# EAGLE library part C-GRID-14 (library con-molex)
CONNECTOR wire to board 2.54 mm (0.100") pitch header
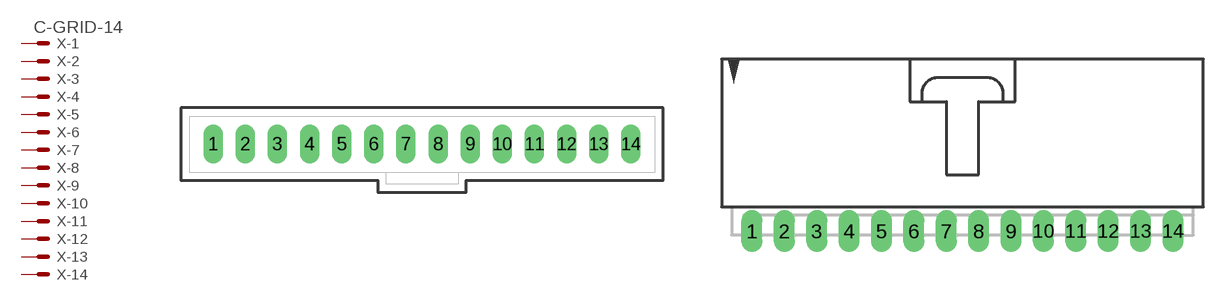
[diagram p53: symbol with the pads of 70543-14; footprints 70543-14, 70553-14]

Designator prefix X; gates -1=MV -2=M -3=M -4=M -5=M -6=M -7=M -8=M -9=M -10=M -11=M -12=M -13=M -14=M

## C-GRID-14-70543 (OC_FARNELL: unknown; OC_NEWARK: unknown)  [70543-14]
1  -1:S  pas
2  -2:S  pas
3  -3:S  pas
4  -4:S  pas
5  -5:S  pas
6  -6:S  pas
7  -7:S  pas
8  -8:S  pas
9  -9:S  pas
10  -10:S  pas
11  -11:S  pas
12  -12:S  pas
13  -13:S  pas
14  -14:S  pas

## C-GRID-14-70553 (OC_FARNELL: unknown; OC_NEWARK: unknown)  [70553-14]
Pads as for 70543-14

## C-GRID-14-74099 (OC_FARNELL: unknown; OC_NEWARK: unknown)  [74099-14]
Pads as for 70543-14

## C-GRID-14-15-91 (OC_FARNELL: unknown; OC_NEWARK: unknown)  [15-91-14]
Pads as for 70543-14

## Footprint 70543-14 (pad centres in mm)
C-Grid SL Connector vertical, 14 pin
drill 1.016 long: 1 -16.51,0; 2 -13.97,0; 3 -11.43,0; 4 -8.89,0; 5 -6.35,0; 6 -3.81,0; 7 -1.27,0; 8 1.27,0; 9 3.81,0; 10 6.35,0; 11 8.89,0; 12 11.43,0; 13 13.97,0; 14 16.51,0

## Footprint 70553-14 (pad centres in mm)
C-Grid SL Connector right angle, 14 pin
drill 1.092 long: 1 -16.51,-7.62; 2 -13.97,-7.62; 3 -11.43,-7.62; 4 -8.89,-7.62; 5 -6.35,-7.62; 6 -3.81,-7.62; 7 -1.27,-7.62; 8 1.27,-7.62; 9 3.81,-7.62; 10 6.35,-7.62; 11 8.89,-7.62; 12 11.43,-7.62; 13 13.97,-7.62; 14 16.51,-7.62

## Footprint 74099-14 (pad centres in mm)
C-Grid SL Connector vertical SMD, 14 pin
smd 1.27 x 3.175: 1 -16.51,-2.223; 2 -13.97,2.223; 3 -11.43,-2.223; 4 -8.89,2.223; 5 -6.35,-2.223; 6 -3.81,2.223; 7 -1.27,-2.223; 8 1.27,2.223; 9 3.81,-2.223; 10 6.35,2.223; 11 8.89,-2.223; 12 11.43,2.223; 13 13.97,-2.223; 14 16.51,2.223

## Footprint 15-91-14 (pad centres in mm)
C-Grid SL Connector right angle SMD, 14 pin
smd 1.651 x 5.334: 1 -16.51,-10.795; 2 -13.97,-10.795; 3 -11.43,-10.795; 4 -8.89,-10.795; 5 -6.35,-10.795; 6 -3.81,-10.795; 7 -1.27,-10.795; 8 1.27,-10.795; 9 3.81,-10.795; 10 6.35,-10.795; 11 8.89,-10.795; 12 11.43,-10.795; 13 13.97,-10.795; 14 16.51,-10.795
hole 3.404 at -17.907,0.838
hole 3.404 at 17.907,0.838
